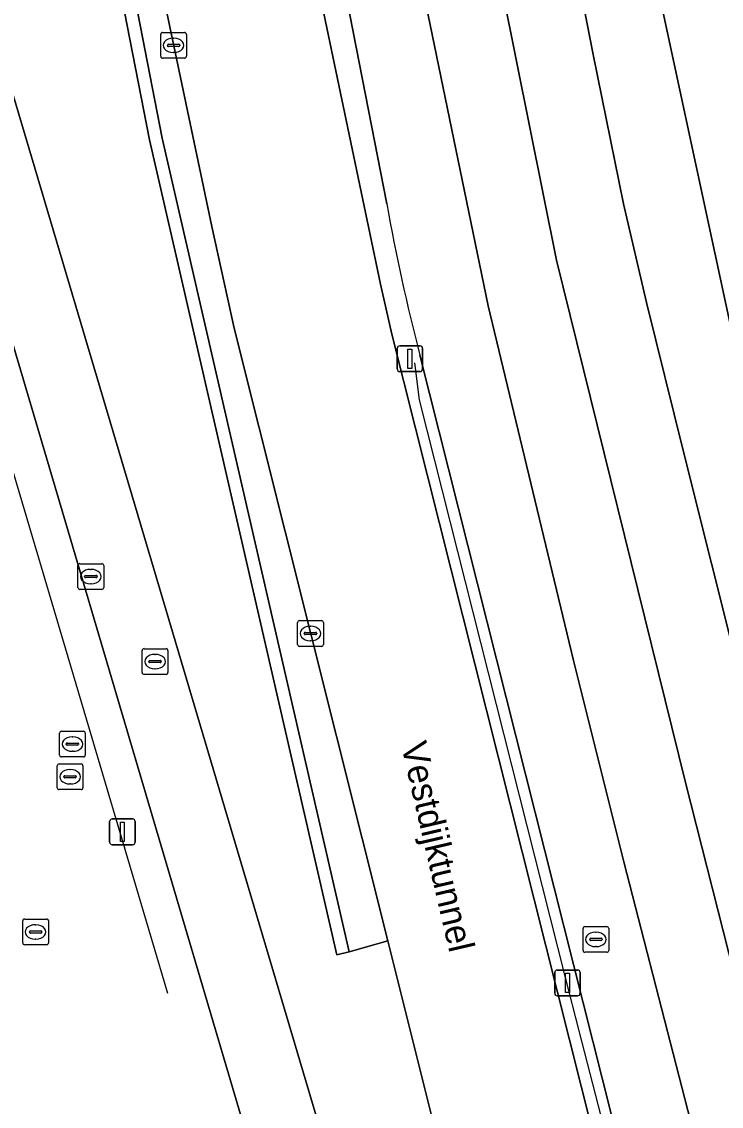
# Model space of a CAD drawing. Extents: x 160806 to 161707, y 383696 to 384148.
# Drawn here: x 161236.82 to 161263.99, y 383784.33 to 383826.47 of the extents above; entities that cross this region are included whole.
import ezdxf

# ---------------------------------------------------------------- set-up
doc = ezdxf.new("R2010")
doc.units = 0
for name, color, linetype in [('IMGEO_Fietspad_open', 7, 'Continuous'), ('IMGEO_Hek', 7, 'Continuous'), ('IMGEO_Kolk', 7, 'Continuous'), ('IMGEO_Lichtmast', 7, 'Continuous'), ('IMGEO_Muur', 7, 'Continuous'), ('IMGEO_Openbare_ruimte_label', 7, 'Continuous'), ('IMGEO_Rijbaan_lokaal_gesloten', 7, 'Continuous'), ('IMGEO_Rioolput', 7, 'Continuous'), ('IMGEO_Verkeerseiland_open', 7, 'Continuous'), ('IMGEO_Voetpad_open', 7, 'Continuous')]:
    doc.layers.add(name, color=color, linetype=linetype)

msp = doc.modelspace()

# ---------------------------------------------------------------- linework, layer by layer
at = {"layer": 'IMGEO_Fietspad_open'}
msp.add_lwpolyline([(161260.786, 383742.458), (161263.932, 383743.92), (161263.352, 383745.857), (161263.192, 383746.41), (161263.05, 383746.885), (161262.122, 383750), (161258.147, 383763.342), (161250.185, 383777.467), (161232.095, 383838.372), (161229.496, 383837.567), (161229.906, 383836.178), (161247.443, 383776.827), (161248.186, 383775.265), (161252.611, 383767.434)], dxfattribs=at)
at = {"layer": 'IMGEO_Hek'}
for points in [[(161257.937, 383789.343), (161252.272, 383811.783), (161252.082, 383813.215)], [(161265.912, 383764.193), (161262.514, 383773.318), (161260.283, 383780.231), (161258.466, 383787.267), (161257.937, 383789.343)]]:
    msp.add_lwpolyline(points, dxfattribs=at)
at = {"layer": 'IMGEO_Kolk'}
for p, q in [((161242.216, 383825.122), (161242.216, 383825.974)), ((161242.291, 383826.048), (161243.143, 383826.048)), ((161242.704, 383825.828), (161242.729, 383825.828)), ((161243.217, 383825.974), (161243.217, 383825.122)), ((161242.475, 383825.542), (161242.475, 383825.554)), ((161242.913, 383825.505), (161242.515, 383825.505)), ((161242.518, 383825.591), (161242.916, 383825.591)), ((161242.959, 383825.554), (161242.959, 383825.542)), ((161243.143, 383825.048), (161242.291, 383825.048)), ((161242.727, 383825.268), (161242.702, 383825.268)), ((161239.005, 383804.487), (161239.005, 383805.339)), ((161239.08, 383805.413), (161239.932, 383805.413)), ((161239.493, 383805.193), (161239.518, 383805.193)), ((161240.006, 383805.339), (161240.006, 383804.487)), ((161239.264, 383804.907), (161239.264, 383804.919)), ((161239.702, 383804.87), (161239.304, 383804.87)), ((161239.307, 383804.956), (161239.705, 383804.956)), ((161239.748, 383804.919), (161239.748, 383804.907)), ((161239.932, 383804.413), (161239.08, 383804.413)), ((161239.516, 383804.633), (161239.491, 383804.633)), ((161247.533, 383802.274), (161247.533, 383803.126)), ((161247.608, 383803.2), (161248.46, 383803.2)), ((161248.021, 383802.98), (161248.046, 383802.98)), ((161248.534, 383803.126), (161248.534, 383802.274)), ((161247.792, 383802.694), (161247.792, 383802.706)), ((161248.23, 383802.657), (161247.832, 383802.657)), ((161247.835, 383802.743), (161248.233, 383802.743)), ((161248.276, 383802.706), (161248.276, 383802.694)), ((161248.46, 383802.2), (161247.608, 383802.2)), ((161248.044, 383802.42), (161248.019, 383802.42)), ((161238.289, 383797.978), (161238.289, 383798.83)), ((161238.364, 383798.904), (161239.216, 383798.904)), ((161239.29, 383798.83), (161239.29, 383797.978)), ((161238.548, 383798.398), (161238.548, 383798.41)), ((161238.986, 383798.361), (161238.588, 383798.361)), ((161238.591, 383798.447), (161238.989, 383798.447)), ((161238.777, 383798.684), (161238.802, 383798.684)), ((161239.032, 383798.41), (161239.032, 383798.398)), ((161239.216, 383797.904), (161238.364, 383797.904)), ((161238.8, 383798.124), (161238.775, 383798.124))]:
    msp.add_line(p, q, dxfattribs=at)
for points in [[(161242.216, 383825.122), (161242.216, 383825.974)], [(161242.291, 383826.048), (161243.143, 383826.048)], [(161243.217, 383825.974), (161243.217, 383825.122)], [(161243.143, 383825.048), (161242.291, 383825.048)], [(161239.005, 383804.487), (161239.005, 383805.339)], [(161239.08, 383805.413), (161239.932, 383805.413)], [(161240.006, 383805.339), (161240.006, 383804.487)], [(161239.932, 383804.413), (161239.08, 383804.413)], [(161247.533, 383802.274), (161247.533, 383803.126)], [(161247.608, 383803.2), (161248.46, 383803.2)], [(161248.534, 383803.126), (161248.534, 383802.274)], [(161248.46, 383802.2), (161247.608, 383802.2)], [(161238.289, 383797.978), (161238.289, 383798.83)], [(161238.364, 383798.904), (161239.216, 383798.904)], [(161239.29, 383798.83), (161239.29, 383797.978)], [(161239.216, 383797.904), (161238.364, 383797.904)]]:
    msp.add_lwpolyline(points, dxfattribs=at)
for centre, radius, start, end in [((161242.293, 383825.972), 0.0765, 91.552, 178.448), ((161242.293, 383825.972), 0.0765, 91.552, 178.448), ((161243.141, 383825.972), 0.0765, 1.552, 88.448), ((161243.141, 383825.972), 0.0765, 1.552, 88.448), ((161242.515, 383825.551), 0.0403, 85.8775, 175.7526), ((161242.512, 383825.541), 0.0366, 178.938, 274.7102), ((161242.916, 383825.548), 0.043, 264.8664, 352.4533), ((161242.92, 383825.553), 0.0386, 1.7309, 96.639), ((161242.293, 383825.124), 0.0765, 181.552, 268.448), ((161242.293, 383825.124), 0.0765, 181.552, 268.448), ((161243.141, 383825.124), 0.0765, 271.552, 358.448), ((161243.141, 383825.124), 0.0765, 271.552, 358.448), ((161239.082, 383805.337), 0.0765, 91.552, 178.448), ((161239.082, 383805.337), 0.0765, 91.552, 178.448), ((161239.93, 383805.337), 0.0765, 1.552, 88.448), ((161239.93, 383805.337), 0.0765, 1.552, 88.448), ((161239.304, 383804.916), 0.0403, 85.8775, 175.7526), ((161239.301, 383804.906), 0.0366, 178.938, 274.7102), ((161239.705, 383804.913), 0.043, 264.8664, 352.4533), ((161239.709, 383804.918), 0.0386, 1.7309, 96.639), ((161239.082, 383804.489), 0.0765, 181.552, 268.448), ((161239.082, 383804.489), 0.0765, 181.552, 268.448), ((161239.93, 383804.489), 0.0765, 271.552, 358.448), ((161239.93, 383804.489), 0.0765, 271.552, 358.448), ((161247.61, 383803.124), 0.0765, 91.552, 178.448), ((161247.61, 383803.124), 0.0765, 91.552, 178.448), ((161248.458, 383803.124), 0.0765, 1.552, 88.448), ((161248.458, 383803.124), 0.0765, 1.552, 88.448), ((161247.832, 383802.703), 0.0403, 85.8775, 175.7526), ((161247.829, 383802.693), 0.0366, 178.938, 274.7102), ((161248.233, 383802.7), 0.043, 264.8664, 352.4533), ((161248.237, 383802.705), 0.0386, 1.7309, 96.639), ((161247.61, 383802.276), 0.0765, 181.552, 268.448), ((161247.61, 383802.276), 0.0765, 181.552, 268.448), ((161248.458, 383802.276), 0.0765, 271.552, 358.448), ((161248.458, 383802.276), 0.0765, 271.552, 358.448), ((161238.366, 383798.828), 0.0765, 91.552, 178.448), ((161238.366, 383798.828), 0.0765, 91.552, 178.448), ((161239.214, 383798.828), 0.0765, 1.552, 88.448), ((161239.214, 383798.828), 0.0765, 1.552, 88.448), ((161238.588, 383798.407), 0.0403, 85.8775, 175.7526), ((161238.585, 383798.397), 0.0366, 178.938, 274.7102), ((161238.989, 383798.404), 0.043, 264.8664, 352.4533), ((161238.993, 383798.409), 0.0386, 1.7309, 96.639), ((161238.366, 383797.98), 0.0765, 181.552, 268.448), ((161238.366, 383797.98), 0.0765, 181.552, 268.448), ((161239.214, 383797.98), 0.0765, 271.552, 358.448), ((161239.214, 383797.98), 0.0765, 271.552, 358.448)]:
    msp.add_arc(centre, radius, start, end, dxfattribs=at)
for centre, major_axis, ratio, start_param, end_param in [((161242.703, 383825.548), (-0.387, 0.002), 0.722429, 4.712389, 7.853982), ((161242.728, 383825.548), (-0.39, 0.002), 0.717154, 1.570796, 4.712389), ((161239.492, 383804.913), (-0.387, 0.002), 0.722429, 4.712389, 7.853982), ((161239.517, 383804.913), (-0.39, 0.002), 0.717154, 1.570796, 4.712389), ((161248.02, 383802.7), (-0.387, 0.002), 0.722429, 4.712389, 7.853982), ((161248.045, 383802.7), (-0.39, 0.002), 0.717154, 1.570796, 4.712389), ((161238.776, 383798.404), (-0.387, 0.002), 0.722429, 4.712389, 7.853982), ((161238.801, 383798.404), (-0.39, 0.002), 0.717154, 1.570796, 4.712389)]:
    msp.add_ellipse(centre, major_axis=major_axis, ratio=ratio, start_param=start_param, end_param=end_param, dxfattribs=at)
at = {"layer": 'IMGEO_Lichtmast'}
for p, q in [((161251.399, 383812.975), (161251.399, 383813.775)), ((161251.399, 383813.775), (161251.399, 383812.975)), ((161251.499, 383813.875), (161252.289, 383813.875)), ((161252.289, 383813.875), (161251.499, 383813.875)), ((161252.389, 383813.775), (161252.389, 383812.975)), ((161252.389, 383812.975), (161252.389, 383813.775)), ((161252.289, 383812.875), (161251.499, 383812.875)), ((161251.499, 383812.875), (161252.289, 383812.875)), ((161240.235, 383794.597), (161240.235, 383795.397)), ((161240.235, 383795.397), (161240.235, 383794.597)), ((161240.335, 383795.497), (161241.125, 383795.497)), ((161241.125, 383795.497), (161240.335, 383795.497)), ((161241.225, 383795.397), (161241.225, 383794.597)), ((161241.225, 383794.597), (161241.225, 383795.397)), ((161241.125, 383794.497), (161240.335, 383794.497)), ((161240.335, 383794.497), (161241.125, 383794.497)), ((161257.516, 383788.726), (161257.516, 383789.526)), ((161257.516, 383789.526), (161257.516, 383788.726)), ((161257.616, 383789.626), (161258.406, 383789.626)), ((161258.406, 383789.626), (161257.616, 383789.626)), ((161258.506, 383789.526), (161258.506, 383788.726)), ((161258.506, 383788.726), (161258.506, 383789.526)), ((161258.406, 383788.626), (161257.616, 383788.626)), ((161257.616, 383788.626), (161258.406, 383788.626))]:
    msp.add_line(p, q, dxfattribs=at)
for points in [[(161251.819, 383813.75), (161251.969, 383813.75), (161251.969, 383813), (161251.819, 383813), (161251.819, 383813.75)], [(161240.655, 383795.372), (161240.805, 383795.372), (161240.805, 383794.622), (161240.655, 383794.622), (161240.655, 383795.372)], [(161257.936, 383789.501), (161258.086, 383789.501), (161258.086, 383788.751), (161257.936, 383788.751), (161257.936, 383789.501)]]:
    msp.add_lwpolyline(points, dxfattribs=at)
for centre, start, end in [((161251.499, 383813.775), 90, 180), ((161251.499, 383813.775), 90, 180), ((161252.289, 383813.775), 0, 90), ((161252.289, 383813.775), 360, 90), ((161251.499, 383812.975), 180, 270), ((161251.499, 383812.975), 180, 270), ((161252.289, 383812.975), 270, 0), ((161252.289, 383812.975), 270, 0), ((161240.335, 383795.397), 90, 180), ((161240.335, 383795.397), 90, 180), ((161241.125, 383795.397), 0, 90), ((161241.125, 383795.397), 360, 90), ((161240.335, 383794.597), 180, 270), ((161240.335, 383794.597), 180, 270), ((161241.125, 383794.597), 270, 0), ((161241.125, 383794.597), 270, 0), ((161257.616, 383789.526), 90, 180), ((161257.616, 383789.526), 90, 180), ((161258.406, 383789.526), 0, 90), ((161258.406, 383789.526), 360, 90), ((161257.616, 383788.726), 180, 270), ((161257.616, 383788.726), 180, 270), ((161258.406, 383788.726), 270, 0), ((161258.406, 383788.726), 270, 0)]:
    msp.add_arc(centre, 0.1, start, end, dxfattribs=at)
at = {"layer": 'IMGEO_Muur'}
msp.add_lwpolyline([(161242.274, 383821.936), (161239.237, 383837.58), (161238.694, 383839.54), (161238.211, 383839.391), (161238.738, 383837.463), (161241.78, 383821.883), (161249.06, 383790.222), (161249.537, 383790.335)], close=True, dxfattribs=at)
msp.add_lwpolyline([(161228.446, 383835.728), (161228.783, 383834.579), (161235.658, 383811.717), (161242.485, 383788.73)], dxfattribs=at)
at = {"layer": 'IMGEO_Rijbaan_lokaal_gesloten'}
for points in [[(161261.069, 383846.45), (161258.098, 383845.532), (161258.808, 383841.755), (161259.905, 383835.909), (161260.887, 383830.892), (161261.458, 383828.087), (161266.67, 383803.83)], [(161258.098, 383845.532), (161255.223, 383844.644), (161255.351, 383843.932), (161259.009, 383825.191), (161260.191, 383819.388), (161261.079, 383815.554), (161262.513, 383809.751), (161264.696, 383801.082), (161268.422, 383786.436), (161271.69, 383774.162), (161272.703, 383771.417)], [(161270.083, 383784.463), (161266.67, 383803.83), (161261.458, 383828.087), (161260.887, 383830.892), (161259.905, 383835.909), (161258.808, 383841.755), (161258.098, 383845.532)], [(161249.469, 383842.867), (161246.641, 383841.994), (161247.543, 383837.06), (161250.994, 383819.392)], [(161272.079, 383751.073), (161271.27, 383753.915), (161267.992, 383764.419), (161264.266, 383778.033), (161260.199, 383793.827), (161258.251, 383801.656), (161254.931, 383815.431), (161252.101, 383829.184), (161249.639, 383841.943), (161249.469, 383842.867)], [(161259.008, 383783.268), (161251.189, 383814.332), (161250.747, 383816.268), (161245.836, 383839.778), (161245.391, 383841.608), (161239.635, 383839.831), (161240.829, 383834.589), (161244.197, 383818.504), (161245.074, 383814.567), (161246.038, 383810.692), (161251.033, 383790.764), (161253.161, 383782.273), (161253.192, 383782.148)], [(161252.284, 383813.518), (161260.112, 383782.451), (161260.508, 383781.031), (161260.992, 383779.593), (161263.566, 383772.013)]]:
    msp.add_lwpolyline(points, dxfattribs=at)
for points in [[(161255.223, 383844.644), (161252.374, 383843.765), (161253.35, 383838.619), (161254.467, 383832.736), (161257.59, 383817.205), (161262.593, 383796.907), (161267.226, 383778.65), (161272.066, 383761.555), (161275.575, 383751.679), (161278.282, 383752.924), (161278.161, 383753.324), (161278.024, 383753.78), (161272.703, 383771.417), (161271.69, 383774.162), (161268.422, 383786.436), (161264.696, 383801.082), (161262.513, 383809.751), (161261.079, 383815.554), (161260.191, 383819.388), (161259.009, 383825.191), (161255.351, 383843.932)], [(161252.374, 383843.765), (161249.469, 383842.867), (161249.639, 383841.943), (161252.101, 383829.184), (161254.931, 383815.431), (161258.251, 383801.656), (161260.199, 383793.827), (161264.266, 383778.033), (161267.992, 383764.419), (161271.27, 383753.915), (161272.079, 383751.073), (161272.227, 383750.635), (161272.358, 383750.199), (161275.575, 383751.679), (161272.066, 383761.555), (161267.226, 383778.65), (161262.593, 383796.907), (161257.59, 383817.205), (161254.467, 383832.736), (161253.35, 383838.619)]]:
    msp.add_lwpolyline(points, close=True, dxfattribs=at)
msp.add_arc((161323.536, 383832.245), 73.672, 190.04698, 194.72543, dxfattribs=at)
at = {"layer": 'IMGEO_Rioolput'}
for p, q in [((161241.497, 383801.185), (161241.497, 383802.037)), ((161241.572, 383802.111), (161242.424, 383802.111)), ((161241.985, 383801.891), (161242.01, 383801.891)), ((161242.498, 383802.037), (161242.498, 383801.185)), ((161241.756, 383801.605), (161241.756, 383801.617)), ((161242.194, 383801.568), (161241.796, 383801.568)), ((161241.799, 383801.654), (161242.197, 383801.654)), ((161242.008, 383801.331), (161241.983, 383801.331)), ((161242.24, 383801.617), (161242.24, 383801.605)), ((161242.424, 383801.111), (161241.572, 383801.111)), ((161238.198, 383796.709), (161238.198, 383797.561)), ((161238.273, 383797.635), (161239.125, 383797.635)), ((161239.199, 383797.561), (161239.199, 383796.709)), ((161238.457, 383797.129), (161238.457, 383797.141)), ((161238.895, 383797.092), (161238.497, 383797.092)), ((161238.5, 383797.178), (161238.898, 383797.178)), ((161238.686, 383797.415), (161238.711, 383797.415)), ((161238.941, 383797.141), (161238.941, 383797.129)), ((161238.709, 383796.855), (161238.684, 383796.855)), ((161239.125, 383796.635), (161238.273, 383796.635)), ((161236.935, 383791.608), (161237.787, 383791.608)), ((161236.86, 383790.682), (161236.86, 383791.534)), ((161237.348, 383791.388), (161237.373, 383791.388)), ((161237.861, 383791.534), (161237.861, 383790.682)), ((161258.616, 383790.392), (161258.616, 383791.244)), ((161258.691, 383791.318), (161259.543, 383791.318)), ((161259.617, 383791.244), (161259.617, 383790.392)), ((161237.119, 383791.102), (161237.119, 383791.114)), ((161237.557, 383791.065), (161237.159, 383791.065)), ((161237.162, 383791.151), (161237.56, 383791.151)), ((161237.371, 383790.828), (161237.346, 383790.828)), ((161237.603, 383791.114), (161237.603, 383791.102)), ((161258.875, 383790.812), (161258.875, 383790.824)), ((161259.313, 383790.775), (161258.915, 383790.775)), ((161258.918, 383790.861), (161259.316, 383790.861)), ((161259.104, 383791.098), (161259.129, 383791.098)), ((161259.359, 383790.824), (161259.359, 383790.812)), ((161237.787, 383790.608), (161236.935, 383790.608)), ((161259.127, 383790.538), (161259.102, 383790.538)), ((161259.543, 383790.318), (161258.691, 383790.318))]:
    msp.add_line(p, q, dxfattribs=at)
for points in [[(161241.497, 383801.185), (161241.497, 383802.037)], [(161241.572, 383802.111), (161242.424, 383802.111)], [(161242.498, 383802.037), (161242.498, 383801.185)], [(161242.424, 383801.111), (161241.572, 383801.111)], [(161238.198, 383796.709), (161238.198, 383797.561)], [(161238.273, 383797.635), (161239.125, 383797.635)], [(161239.199, 383797.561), (161239.199, 383796.709)], [(161239.125, 383796.635), (161238.273, 383796.635)], [(161236.935, 383791.608), (161237.787, 383791.608)], [(161236.86, 383790.682), (161236.86, 383791.534)], [(161237.861, 383791.534), (161237.861, 383790.682)], [(161258.616, 383790.392), (161258.616, 383791.244)], [(161258.691, 383791.318), (161259.543, 383791.318)], [(161259.617, 383791.244), (161259.617, 383790.392)], [(161237.787, 383790.608), (161236.935, 383790.608)], [(161259.543, 383790.318), (161258.691, 383790.318)]]:
    msp.add_lwpolyline(points, dxfattribs=at)
for centre, radius, start, end in [((161241.574, 383802.035), 0.0765, 91.552, 178.448), ((161241.574, 383802.035), 0.0765, 91.552, 178.448), ((161242.422, 383802.035), 0.0765, 1.552, 88.448), ((161242.422, 383802.035), 0.0765, 1.552, 88.448), ((161241.796, 383801.614), 0.0403, 85.8775, 175.7526), ((161241.793, 383801.604), 0.0366, 178.938, 274.7102), ((161242.197, 383801.611), 0.043, 264.8664, 352.4533), ((161242.201, 383801.616), 0.0386, 1.7309, 96.639), ((161241.574, 383801.187), 0.0765, 181.552, 268.448), ((161241.574, 383801.187), 0.0765, 181.552, 268.448), ((161242.422, 383801.187), 0.0765, 271.552, 358.448), ((161242.422, 383801.187), 0.0765, 271.552, 358.448), ((161238.275, 383797.559), 0.0765, 91.552, 178.448), ((161238.275, 383797.559), 0.0765, 91.552, 178.448), ((161239.123, 383797.559), 0.0765, 1.552, 88.448), ((161239.123, 383797.559), 0.0765, 1.552, 88.448), ((161238.497, 383797.138), 0.0403, 85.8775, 175.7526), ((161238.494, 383797.128), 0.0366, 178.938, 274.7102), ((161238.898, 383797.135), 0.043, 264.8664, 352.4533), ((161238.902, 383797.14), 0.0386, 1.7309, 96.639), ((161238.275, 383796.711), 0.0765, 181.552, 268.448), ((161238.275, 383796.711), 0.0765, 181.552, 268.448), ((161239.123, 383796.711), 0.0765, 271.552, 358.448), ((161239.123, 383796.711), 0.0765, 271.552, 358.448), ((161236.937, 383791.532), 0.0765, 91.552, 178.448), ((161236.937, 383791.532), 0.0765, 91.552, 178.448), ((161237.785, 383791.532), 0.0765, 1.552, 88.448), ((161237.785, 383791.532), 0.0765, 1.552, 88.448), ((161258.693, 383791.242), 0.0765, 91.552, 178.448), ((161258.693, 383791.242), 0.0765, 91.552, 178.448), ((161259.541, 383791.242), 0.0765, 1.552, 88.448), ((161259.541, 383791.242), 0.0765, 1.552, 88.448), ((161237.159, 383791.111), 0.0403, 85.8775, 175.7526), ((161237.156, 383791.101), 0.0366, 178.938, 274.7102), ((161237.56, 383791.108), 0.043, 264.8664, 352.4533), ((161237.564, 383791.113), 0.0386, 1.7309, 96.639), ((161258.915, 383790.821), 0.0403, 85.8775, 175.7526), ((161258.912, 383790.811), 0.0366, 178.938, 274.7102), ((161259.316, 383790.818), 0.043, 264.8664, 352.4533), ((161259.32, 383790.823), 0.0386, 1.7309, 96.639), ((161236.937, 383790.684), 0.0765, 181.552, 268.448), ((161236.937, 383790.684), 0.0765, 181.552, 268.448), ((161237.785, 383790.684), 0.0765, 271.552, 358.448), ((161237.785, 383790.684), 0.0765, 271.552, 358.448), ((161258.693, 383790.394), 0.0765, 181.552, 268.448), ((161258.693, 383790.394), 0.0765, 181.552, 268.448), ((161259.541, 383790.394), 0.0765, 271.552, 358.448), ((161259.541, 383790.394), 0.0765, 271.552, 358.448)]:
    msp.add_arc(centre, radius, start, end, dxfattribs=at)
for centre, major_axis, ratio, start_param, end_param in [((161241.984, 383801.611), (-0.387, 0.002), 0.722429, 4.712389, 7.853982), ((161242.009, 383801.611), (-0.39, 0.002), 0.717154, 1.570796, 4.712389), ((161238.685, 383797.135), (-0.387, 0.002), 0.722429, 4.712389, 7.853982), ((161238.71, 383797.135), (-0.39, 0.002), 0.717154, 1.570796, 4.712389), ((161237.347, 383791.108), (-0.387, 0.002), 0.722429, 4.712389, 7.853982), ((161237.372, 383791.108), (-0.39, 0.002), 0.717154, 1.570796, 4.712389), ((161259.103, 383790.818), (-0.387, 0.002), 0.722429, 4.712389, 7.853982), ((161259.128, 383790.818), (-0.39, 0.002), 0.717154, 1.570796, 4.712389)]:
    msp.add_ellipse(centre, major_axis=major_axis, ratio=ratio, start_param=start_param, end_param=end_param, dxfattribs=at)
at = {"layer": 'IMGEO_Verkeerseiland_open'}
for points in [[(161247.543, 383837.06), (161246.641, 383841.994), (161245.391, 383841.608), (161245.836, 383839.778), (161250.747, 383816.268), (161251.189, 383814.332), (161259.008, 383783.268)], [(161250.994, 383819.392), (161247.543, 383837.06)], [(161263.566, 383772.013), (161260.992, 383779.593), (161260.508, 383781.031), (161260.112, 383782.451), (161252.284, 383813.518)]]:
    msp.add_lwpolyline(points, dxfattribs=at)
msp.add_lwpolyline([(161244.197, 383818.504), (161240.829, 383834.589), (161239.635, 383839.831), (161238.694, 383839.54), (161239.237, 383837.58), (161242.274, 383821.936), (161249.537, 383790.335), (161251.033, 383790.764), (161246.038, 383810.692), (161245.074, 383814.567)], close=True, dxfattribs=at)
msp.add_arc((161323.536, 383832.245), 73.672, 190.04698, 194.72543, dxfattribs=at)
at = {"layer": 'IMGEO_Voetpad_open'}
for points in [[(161241.78, 383821.883), (161238.738, 383837.463), (161238.211, 383839.391), (161235.276, 383850.128), (161232.239, 383849.441), (161231.99, 383849.371)], [(161229.853, 383845.993), (161229.876, 383845.844), (161230.682, 383843.131), (161232.095, 383838.372), (161250.185, 383777.467), (161258.147, 383763.342), (161258.675, 383763.473), (161258.169, 383765.179), (161257.975, 383765.127), (161257.234, 383767.212), (161253.777, 383776.222)], [(161252.655, 383779.631), (161252.053, 383781.983), (161253.161, 383782.273), (161251.033, 383790.764), (161249.537, 383790.335), (161249.06, 383790.222), (161241.78, 383821.883)]]:
    msp.add_lwpolyline(points, dxfattribs=at)
msp.add_lwpolyline([(161229.906, 383836.178), (161228.446, 383835.728), (161228.783, 383834.579), (161221.311, 383832.189), (161243.065, 383757.002), (161239.522, 383755.972), (161240.864, 383751.327), (161236.286, 383750), (161191.93, 383737.142), (161183.813, 383734.789), (161180.174, 383733.799), (161180.701, 383732.163), (161183.823, 383722.462), (161184.529, 383720.269), (161185.806, 383720.507), (161185.94, 383720.532), (161192.037, 383722.084), (161228.633, 383732.395), (161240.638, 383736.519), (161256.653, 383743.919), (161257.809, 383744.453), (161247.443, 383776.827)], close=True, dxfattribs=at)

# ---------------------------------------------------------------- texts
at = {"layer": 'IMGEO_Openbare_ruimte_label'}
msp.add_text('Vestdijktunnel', height=1, rotation=283.1191, dxfattribs=at).set_placement((161251.547, 383798.367))

doc.saveas('drawing.dxf')
